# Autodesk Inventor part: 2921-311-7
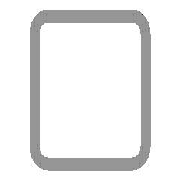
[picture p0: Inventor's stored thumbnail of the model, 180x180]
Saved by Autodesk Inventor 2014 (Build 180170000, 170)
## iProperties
IsCustomPart: 1
Company: NHTSA/VRTC
Created: 2012-02
Part Number: 2921-311-7
Material: Steel, Mild
Description: BENCH FRAME TUBE #7
Document SubType Name: Modeling
Standard: AISC
Designer: Dave Walker
Standards Organization: ANSI
Language: en-US
Size Designation: 1-1/2x1-1/2x1/8 - 21.31488330958224
Categories: <MemberInstance><Categories><Category DisplayName="Structural Shapes" InternalName="089c4875-fa83-4c05-b084-43b9cc11f5ed" Mnemonic="GRDR"><CategoryParameter Dis
Stock Number: T.S. 1 1/2 x 1 1/2 x 1/8 x 545.6mm (21.31")
Density: 1 g/cm^3
Project: CHILD SIDE IMPACT SLED
Appearance: Steel
G_L: 21.315 in
Author: Dave Walker
Title: Bench Frame Tube #7
Subject: Child Side Impact Sled
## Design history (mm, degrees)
node "Start plane"
node "End plane"
sketch "Sketch"
  geometry: L1 (-19.05, -12.7)-(-19.05, 12.7); L2 (-12.7, 19.05)-(12.7, 19.05); L3 (19.05, 12.7)-(19.05, -12.7); L4 (12.7, -19.05)-(-12.7, -19.05); L5 (-12.7, 15.875)-(12.7, 15.875); L6 (15.875, 12.7)-(15.875, -12.7); L7 (12.7, -15.875)-(-12.7, -15.875); L8 (-15.875, -12.7)-(-15.875, 12.7); L9 (0, 36.948)-(0, -36.948) reference; L10 (-23.079, 0)-(23.079, 0) reference; A1 r 6.35 centre (-12.7, -12.7) between (-19.05, -12.7) and (-12.7, -19.05); A2 r 6.35 centre (-12.7, 12.7) between (-12.7, 19.05) and (-19.05, 12.7); A3 r 6.35 centre (12.7, 12.7) between (19.05, 12.7) and (12.7, 19.05); A4 r 6.35 centre (12.7, -12.7) between (12.7, -19.05) and (19.05, -12.7); A5 r 3.175 centre (-12.7, 12.7) between (-12.7, 15.875) and (-15.875, 12.7); A6 r 3.175 centre (12.7, 12.7) between (15.875, 12.7) and (12.7, 15.875); A7 r 3.175 centre (12.7, -12.7) between (12.7, -15.875) and (15.875, -12.7); A8 r 3.175 centre (-12.7, -12.7) between (-15.875, -12.7) and (-12.7, -15.875)
  constraints: 16 end point, 16 point on circle, 8 centre point, 8 tangent, 4 parallel, 3 equal radius, 2 perpendicular, 7 other
  dimensions: "d10" = 38.1 distance between parallel lines of L2 L4 (= G_H); "d11" = 38.1 distance between parallel lines of L1 L3 (= G_W); "d12" = 3.175 distance between parallel lines of L3 L6 (= G_T); "d15" = 19.05 distance between parallel lines of L2 L10 (= 0.5 x d10); "d16" = 19.05 distance between parallel lines of L9 L3 (= 0.5 x d11); "d17" = 6.35 radius of A1 (= G_IR)
extrude "Body" new body sketch "Sketch" stored distance "d3" = 541.39804 (= G_L); taper "d4" = 0 deg
node "Driven Length"
  sketch "Sketch3"
    geometry: L1 (0, 0)-(10, 0) reference
    constraints: 2 end point, 1 horizontal
  workplane "Work Plane3"
  sketch "Sketch4"
    geometry: L1 (-2, 0)-(12, 0) reference; L2 (-2, 541.398)-(12, 541.398) reference
    dimensions: "d19" = 541.39804 distance between parallel lines of L1 L2 (derived)
sketch "Sketch5"
  geometry: L1 (0, 25.4)-(0, 0) reference; L2 (541.398, 25.4)-(541.398, 0) reference; L3 (541.398, -6.35)-(0, -6.35) reference; L4 (56.837, -6.35)-(0, 9.092); L5 (0, 9.092)-(0, -6.35); L6 (0, -6.35)-(56.837, -6.35); 2 further points
  constraints: 6 end point, 2 point on line, 1 perpendicular
  dimensions: "d20" = 484.56133 distance from line of L2 L4.start; "d21" = 15.2 deg angle of L6 L4
extrude "Extrusion2" cut sketch "Sketch5" stored distance "d22" = 25.4; taper "d23" = 0 deg
sketch "Sketch6"
  geometry: L1 (0, 0)-(0, -16.308) reference; L2 (541.398, 6.35)-(0, 6.35) reference; L3 (0, -16.308)-(6.156, 6.35); L4 (6.156, 6.35)-(0, 6.35); L5 (0, 6.35)-(0, -16.308); 1 further point
  constraints: 6 end point, 2 collinear, 1 point on line
  dimensions: "d24" = 15.2 deg angle of L3 L5
extrude "Extrusion3" cut sketch "Sketch6" stored distance "d25" = 25.4; taper "d26" = 0 deg
sketch "Sketch7"
  geometry: C1 r 3.569 at (12.738, -47.527) reference; C2 r 3.569 at (12.738, -201.627) reference; C3 r 3.569 at (12.738, -352.627) reference; 7 further points
  constraints: 3 coincident
hole "Hole1" sketch "Sketch7" diameter "d30" = 4.9784; stored, may be unused: countersink angle "d34" = 82 deg, drill point angle "d36" = 118 deg; dims "d31" = 19.05, "d32" = 9.525, "d33" = 6.35, "d35" = 3.175
workplane "Work Plane4"
body "Solid1"
node "Reference4"
node "Reference5"
node "Reference6"
other parameters: "G_W" = 38.1 [user parameter; used in 1 equation term], "G_H" = 38.1 [user parameter; used in 1 equation term], "G_T" = 3.175 [user parameter; used in 1 equation term], "G_IR" = 6.35 [user parameter; used in 1 equation term], "G_L" = 541.39804 (= d19) [user parameter; used in 1 equation term], "G_OFFSET_START" = 0 [user parameter; used in 1 equation term], "G_OFFSET_END" = 0 [user parameter; used in 1 equation term], "d13" = 0 (computed from G_OFFSET_START), "d14" = 541.39804 (= G_OFFSET_END + B_L), "B_L" = 541.39804 [user parameter; used in 1 equation term], "d18" = 90 deg
